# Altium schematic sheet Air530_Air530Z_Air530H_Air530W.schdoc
size 193 x 99 mm
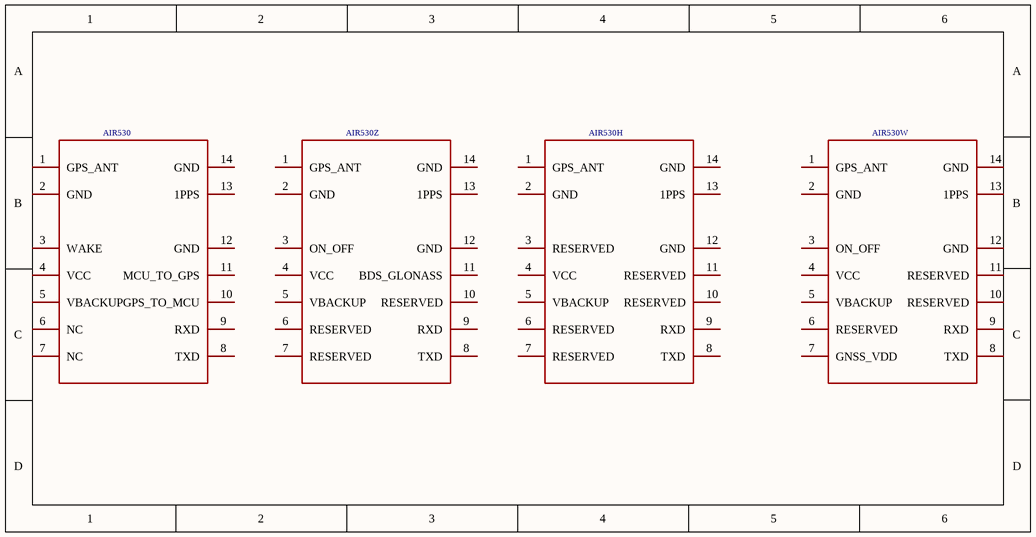
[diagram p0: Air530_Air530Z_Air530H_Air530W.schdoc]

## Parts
U1  AIR530H
U2  AIR530
U3  AIR530Z
U4  AIR530W

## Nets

Not connected (* = marked no-connect by the designer): U1 1(GPS_ANT) 2(GND) 3(RESERVED) 4(VCC) 5(VBACKUP) 6(RESERVED) 7(RESERVED) 8(TXD) 9(RXD) 10(RESERVED) 11(RESERVED) 12(GND) 13(1PPS) 14(GND); U2 1(GPS_ANT) 2(GND) 3(WAKE) 4(VCC) 5(VBACKUP) 6(NC) 7(NC) 8(TXD) 9(RXD) 10(GPS_TO_MCU) 11(MCU_TO_GPS) 12(GND) 13(1PPS) 14(GND); U3 1(GPS_ANT) 2(GND) 3(ON_OFF) 4(VCC) 5(VBACKUP) 6(RESERVED) 7(RESERVED) 8(TXD) 9(RXD) 10(RESERVED) 11(BDS_GLONASS) 12(GND) 13(1PPS) 14(GND); U4 1(GPS_ANT) 2(GND) 3(ON_OFF) 4(VCC) 5(VBACKUP) 6(RESERVED) 7(GNSS_VDD) 8(TXD) 9(RXD) 10(RESERVED) 11(RESERVED) 12(GND) 13(1PPS) 14(GND)

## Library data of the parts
U1 = AIR530H: Manufacture: Luat; Geometry_Height: 2.3 MM; Add into BOM: yes; Origin Footprint: AIR530
U2 = AIR530: Manufacture: Luat; Geometry_Height: 2.3MM; Add into BOM: yes
U3 = AIR530Z: Manufacture: Luat; Geometry_Height: 2.3mm; Add into BOM: yes; Origin Footprint: AIR530
U4 = AIR530W: Manufacture: Luat; Manufacturer P/N: Air530H; Geometry_Height: 2.3 MM; Add into BOM: yes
